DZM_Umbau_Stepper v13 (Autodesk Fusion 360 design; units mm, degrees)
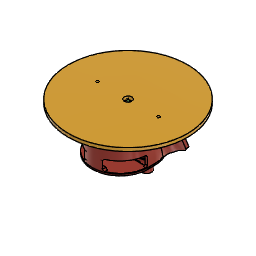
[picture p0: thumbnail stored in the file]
sketch "Skizze1" plane through (0, 0, 0) normal (0, 0, 1) x axis (1, 0, 0)
  line L1 (20.25, 0) -> (-20.25, 0)
  circle C1 centre (0, 0) radius 39.5
  circle C2 centre (0, 0) radius 2.5
  circle C3 centre (-20.25, 0) radius 0.925
  circle C4 centre (20.25, 0) radius 0.925
  point P1 (0, 0)
  point P2 (0, 0)
  point P3 (0, 0)
  point P4 (-20.25, 0)
  point P6 (-20.25, 0)
  point P5 (20.25, 0)
  point P7 (20.25, 0)
  point P8 (-20.25, 0)
  point P9 (20.25, 0)
  coincident P1 P2
  coincident P1 P3
  coincident P4 P6
  coincident P5 P7
  horizontal L1
  coincident P4 P8
  coincident P7 P9
  dimension "d1" diameter C1 = 79
  dimension "d2" diameter C2 = 5
  dimension "d3" distance P4 P5 = 40.5
  dimension "d4" distance P2 P4 = 20.25 (= "( 40.5 / 2 ) * 1 mm")
  dimension "d5" diameter C3 = 1.85
  dimension "d6" diameter C4 = 1.85
extrude "Extrusion1" new body sketch "Skizze1" profile of C1 C2 C3 C4 along normal blind 2.2 bodies "Tachoscheibe"
sketch "Skizze2" plane through (0, 0, 0) normal (0, 1, 0) x axis (1, 0, 0)
  circle C1 centre (-8.25, 8.8116) radius 1.3
  circle C2 centre (8.25, 8.8116) radius 1.3
  circle C3 centre (0, -10.5) radius 1.3
  circle C4 centre (0, 6.3) radius 0.95
  circle C5 centre (-13.5, 0) radius 1
  circle C6 centre (13.5, 0) radius 1
  circle C7 centre (0, 0) radius 16
  circle C8 centre (12, 3.9) radius 0.25
  circle C9 centre (12, -3.9) radius 0.25
  circle C10 centre (-12, 3.9) radius 0.25
  circle C11 centre (-12, -3.9) radius 0.25
  point P1 (0, 0)
  point P4 (0, -10.5)
  point P5 (0, 6.3)
  point P8 (0, 0)
  point P6 (-13.5, 0)
  point P7 (13.5, 0)
  point P2 (-8.25, 8.8116)
  point P3 (8.25, 8.8116)
  point P9 (12, 3.9)
  point P10 (12, -3.9)
  point P11 (-12, 3.9)
  point P12 (-12, -3.9)
  equal C1 C3
  equal C2 C3
  vertical P1 P4
  vertical P1 P5
  coincident P1 P8
  horizontal P6 P8
  horizontal P7 P8
  equal C8 C9
  equal C8 C10
  equal C8 C11
  dimension "d9" distance P2 P3 = 16.5
  dimension "d10" distance P1 P2 = 8.25 (= "( 16.5 / 2 ) * 1 mm")
  dimension "d11" distance P2 P4 = 21
  dimension "d12" distance P3 P4 = 21
  dimension "d13" diameter C3 = 2.6
  dimension "d18" diameter C4 = 1.9
  dimension "d19" distance P6 P7 = 27
  dimension "d20" distance P1 P6 = 13.5 (= "( 27 / 2 ) * 1 mm")
  dimension "d21" diameter C5 = 2
  dimension "d22" diameter C6 = 2
  dimension "d23" diameter C7 = 32
  dimension "d24" distance P1 P4 = 10.5
  dimension "d25" distance P9 P10 = 7.8
  dimension "d26" distance P1 P9 = 3.9 (= "( 7.8 / 2 ) * 1 mm")
  dimension "d27" distance P11 P12 = 7.8
  dimension "d28" distance P1 P11 = 3.9 (= "( 7.8 / 2 ) * 1 mm")
  dimension "d29" distance P1 P10 = 12
  dimension "d30" distance P8 P12 = 12
  dimension "d31" diameter C8 = 0.5
  dimension "d32" distance P8 P11 = 12
  dimension "d33" distance P8 P9 = 12
  dimension "d201" distance P1 P5 = 6.3
extrude "Extrusion2" new body sketch "Skizze2" along normal blind 9.5 bodies "Steppermotor"
extrude "Extrusion3" add sketch "Skizze2" profile of C1 C2 C3 along normal blind 13.3 (= "3.8 mm + 9.5 mm")
extrude "Extrusion4" add sketch "Skizze2" profile of C4 along normal blind 11.4 (= "9.5 mm + 1.9 mm")
sketch "Skizze3" plane through (0, 11.4, 0) normal (0, 1, 0) x axis (-1, 0, 0)
  circle C1 centre (0, -6.3) radius 0.95
  circle C2 centre (0, -6.3) radius 0.5
  concentric C1 C2
  dimension "d40" diameter C2 = 1
extrude "Extrusion5" add sketch "Skizze3" profile of C2 along normal blind 9
extrude "Extrusion6" add sketch "Skizze2" profile of C8 C9 C10 C11 along normal blind 12.5 (= "9.5 mm + 3 mm")
move "Verschieben1"
sketch "Skizze4" plane through (0, 0, -3.8628) normal (0, 0, 1) x axis (-1, 0, 0)
  circle C1 centre (0, 16.0521) radius 1.3
  circle C2 centre (-8.25, -3.2595) radius 1.3
  circle C3 centre (-12, 9.4521) radius 0.25
  circle C4 centre (0, -0.7479) radius 0.95
  circle C5 centre (13.5, 5.5521) radius 1
  circle C6 centre (-12, 1.6521) radius 0.25
  circle C7 centre (12, 9.4521) radius 0.25
  circle C8 centre (-13.5, 5.5521) radius 1
  circle C9 centre (12, 1.6521) radius 0.25
  circle C10 centre (8.25, -3.2595) radius 1.3
  circle C11 centre (0, 5.5521) radius 16
  circle C12 centre (13.5, 5.5521) radius 0.85
  circle C13 centre (-13.5, 5.5521) radius 0.85
  concentric C5 C12
  concentric C8 C13
  dimension "d47" diameter C12 = 1.7
  dimension "d48" diameter C13 = 1.7
extrude "Extrusion8" new body sketch "Skizze4" along normal blind 8.5
move "Verschieben3"
sketch "Skizze5" plane through (0, 0, 4.6372) normal (0, 0, -1) x axis (1, 0, 0)
  circle C1 centre (20.25, -0.7479) radius 0.925
  circle C2 centre (0, -0.7479) radius 2.5
  circle C3 centre (-20.25, -0.7479) radius 0.925
  circle C4 centre (0, -0.7479) radius 39.5
  circle C5 centre (20.25, -0.7479) radius 0.925
  circle C6 centre (-20.25, -0.7479) radius 0.925
  circle C7 centre (0, 5.5521) radius 16
  circle C8 centre (-20.25, -0.7479) radius 0.8
  circle C9 centre (20.25, -0.7479) radius 0.8
  circle C10 centre (-20.25, -0.7479) radius 3
  circle C11 centre (20.25, -0.7479) radius 3
  circle C12 centre (0, 4) radius 18.25
  arc A1 centre (-30.2824, 11.7161) radius 13 clockwise from (-17.6849, 8.5062) to (-22.1311, 1.5891)
  arc A2 centre (-21.8165, -13.1494) radius 9.5 clockwise from (-20.626, -3.7243) to (-14.3478, -7.2784)
  arc A3 centre (30.2824, 11.7161) radius 13 clockwise from (22.1311, 1.5891) to (17.6849, 8.5062)
  arc A4 centre (21.8165, -13.1494) radius 9.5 clockwise from (14.3478, -7.2784) to (20.626, -3.7243)
  point P1 (0, 0)
  point P12 (0, 4)
  point P14 (-22.1311, 1.5891)
  point P13 (-17.6849, 8.5062)
  point P17 (-14.3478, -7.2784)
  point P16 (-20.626, -3.7243)
  point P20 (22.1311, 1.5891)
  point P19 (17.6849, 8.5062)
  point P23 (20.626, -3.7243)
  point P22 (14.3478, -7.2784)
  concentric C6 C8
  concentric C5 C9
  concentric C6 C10
  concentric C9 C11
  vertical P1 P12
  tangent C12 A1
  coincident C10 P14
  coincident C12 P13
  tangent C12 A2
  coincident C12 P17
  coincident C10 P16
  tangent C12 A3
  coincident C11 P20
  coincident C12 P19
  tangent C12 A4
  coincident C11 P23
  coincident C12 P22
  tangent C10 A1
  tangent C10 A2
  tangent C11 A4
  tangent C11 A3
  dimension "d51" diameter C8 = 1.6
  dimension "d52" diameter C9 = 1.6
  dimension "d53" diameter C10 = 6
  dimension "d54" diameter C11 = 6
  dimension "d55" diameter C12 = 36.5
  dimension "d56" distance P1 P12 = 4
  dimension "d57" radius A4 = 9.5
  dimension "d58" radius A2 = 9.5
  dimension "d59" radius A3 = 13
  dimension "d60" radius A1 = 13
sketch "Skizze6" plane through (0, 0, 4.6372) normal (0, 0, 1) x axis (-1, 0, 0)
  circle C1 centre (8.25, -3.2595) radius 1.3
  circle C2 centre (0, -0.7479) radius 0.95
  circle C3 centre (-8.25, -3.2595) radius 1.3
  circle C4 centre (13.5, 5.5521) radius 0.85
  circle C5 centre (0, 16.0521) radius 1.3
  circle C6 centre (-13.5, 5.5521) radius 0.85
  circle C7 centre (0, 5.5521) radius 16
  arc A1 centre (21.8165, -13.1494) radius 9.5 clockwise from (14.3478, -7.2784) to (20.626, -3.7243)
  circle C8 centre (0, 4) radius 18.25
  circle C9 centre (20.25, -0.7479) radius 3
  arc A2 centre (30.2824, 11.7161) radius 13 clockwise from (22.1311, 1.5891) to (17.6849, 8.5062)
  arc A3 centre (-30.2824, 11.7161) radius 13 clockwise from (-17.6849, 8.5062) to (-22.1311, 1.5891)
  circle C10 centre (-20.25, -0.7479) radius 3
  arc A4 centre (-21.8165, -13.1494) radius 9.5 clockwise from (-20.626, -3.7243) to (-14.3478, -7.2784)
  circle C11 centre (-20.25, -0.7479) radius 0.8
  circle C12 centre (20.25, -0.7479) radius 0.8
extrude "Extrusion9" add sketch "Skizze6" profile of C7 A1 C8 C9 A2 A3 C10 A4 C11 C12 against normal blind 3
sketch "Skizze7" plane through (0, 0, -3.8628) normal (0, 0, 1) x axis (-1, 0, 0)
  line L1 (-1.5, 0.6521) -> (-13.5, 0.6521)
  line L2 (-1.5, 10.4521) -> (-1.5, 0.6521)
  line L3 (-13.5, 10.4521) -> (-1.5, 10.4521)
  line L4 (-13.5, 0.6521) -> (-13.5, 10.4521)
  line L5 (13.5, 0.6521) -> (1.5, 0.6521)
  line L6 (13.5, 10.4521) -> (13.5, 0.6521)
  line L7 (1.5, 10.4521) -> (13.5, 10.4521)
  line L8 (1.5, 0.6521) -> (1.5, 10.4521)
  line L9 (-5.5, 0.6521) -> (-1.5, 0.6521)
  line L10 (-5.5, -10.8203) -> (-5.5, 0.6521)
  line L11 (-1.5, -10.8203) -> (-5.5, -10.8203)
  line L12 (-1.5, 0.6521) -> (-1.5, -10.8203)
  line L13 (5.5, 0.6521) -> (1.5, 0.6521)
  line L14 (5.5, -11.2243) -> (5.5, 0.6521)
  line L15 (1.5, -11.2243) -> (5.5, -11.2243)
  line L16 (1.5, 0.6521) -> (1.5, -11.2243)
  circle C1 centre (-13.5, 5.5521) radius 2
  circle C2 centre (13.5, 5.5521) radius 2
  circle C3 centre (0, 0) radius 1.3
  point P2 (-13.5, 5.5521)
  point P8 (-13.5, 5.5521)
  point P3 (13.5, 5.5521)
  point P9 (13.5, 5.5521)
  point P1 (0, 0)
  point P24 (0, 0)
  point P5 (-12, 1.6521)
  point P4 (-12, 9.4521)
  point P7 (12, 9.4521)
  point P6 (12, 1.6521)
  point P14 (1.5, 0.6521)
  point P15 (13.5, 0.6521)
  point P12 (-1.5, 10.4521)
  point P13 (-13.5, 10.4521)
  point P11 (-1.5, 0.6521)
  point P18 (-5.5, 0.6521)
  point P21 (5.5, 0.6521)
  coincident P2 P8
  coincident P3 P9
  horizontal L1
  vertical L2
  horizontal L3
  vertical L4
  horizontal L5
  vertical L6
  horizontal L7
  vertical L8
  coincident P2 L4
  coincident P3 L6
  horizontal L9
  vertical L10
  horizontal L11
  vertical L12
  horizontal L13
  vertical L14
  horizontal L15
  vertical L16
  coincident P1 P24
  dimension "d63" diameter C1 = 4
  dimension "d64" diameter C2 = 4
  dimension "d65" distance P5 L1 = 1
  dimension "d66" distance P4 L3 = 1
  dimension "d67" distance P7 L7 = 1
  dimension "d68" distance P6 L5 = 1
  dimension "d69" distance P14 P15 = 12
  dimension "d70" distance P12 P13 = 12
  dimension "d73" distance P11 P18 = 4
  dimension "d74" distance P14 P21 = 4
  dimension "d79" diameter C3 = 2.6
extrude "Extrusion10" cut sketch "Skizze7" profile of C1 C2 L1 L2 L3 L4 L5 L6 L7 L8 L9 L10 L11 L12 L13 L14 L15 L16 along normal blind 2
fillet "Abrundung1" radius 2.5
fillet "Abrundung2" radius 1
extrude "Extrusion11" cut sketch "Skizze7" profile of C3 along normal blind 9
work_plane "Arbeitsebene1" AlongDistance 26.2
sketch "Skizze8" plane through (0, 0, -21.5628) normal (0, 0, -1) x axis (-1, 0, 0)
  line L1 (2.0207, 16.0535) -> (4.0415, 12.5535)
  line L2 (-2.0207, 16.0535) -> (2.0207, 16.0535)
  line L3 (-4.0415, 12.5535) -> (-2.0207, 16.0535)
  line L4 (-2.0207, 9.0535) -> (-4.0415, 12.5535)
  line L5 (2.0207, 9.0535) -> (-2.0207, 9.0535)
  line L6 (4.0415, 12.5535) -> (2.0207, 9.0535)
  line L7 (-9.4, 2.0207) -> (-9.4, -2.0207)
  line L8 (-12.9, 4.0415) -> (-9.4, 2.0207)
  line L9 (-16.4, 2.0207) -> (-12.9, 4.0415)
  line L10 (-16.4, -2.0207) -> (-16.4, 2.0207)
  line L11 (-12.9, -4.0415) -> (-16.4, -2.0207)
  line L12 (-9.4, -2.0207) -> (-12.9, -4.0415)
  line L13 (12.9, -4.0415) -> (9.4, -2.0207)
  line L14 (16.4, -2.0207) -> (12.9, -4.0415)
  line L15 (16.4, 2.0207) -> (16.4, -2.0207)
  line L16 (12.9, 4.0415) -> (16.4, 2.0207)
  line L17 (9.4, 2.0207) -> (12.9, 4.0415)
  line L18 (9.4, -2.0207) -> (9.4, 2.0207)
  line L19 (0, 4) -> (0, -5)
  line L20 (8, 0) -> (-6, 0)
  line L21 (18.5, 0) -> (18.5, -4.5)
  line L22 (-18.5, 0) -> (-18.5, -4.5)
  circle C1 centre (0, 0) radius 18.5
  circle C2 centre (12.9, 0) radius 3.5
  circle C3 centre (-12.9, 0) radius 3.5
  circle C4 centre (0, 12.5535) radius 3.5
  circle C5 centre (0, -4.5) radius 18.5
  point P1 (0, 0)
  point P2 (0, 0)
  point P5 (0, 12.5535)
  point P4 (-12.9, 0)
  point P12 (0, 12.5535)
  point P19 (-12.9, 0)
  point P3 (12.9, 0)
  point P26 (12.9, 0)
  point P31 (0, -4.5)
  point P32 (18.5, -4.5)
  point P33 (18.5, 0)
  point P34 (-18.5, -4.5)
  point P35 (-18.5, 0)
  point P16 (-16.4, 2.0207)
  coincident P1 P2
  vertical P1 P5
  horizontal P1 P4
  coincident P5 P12
  coincident P4 P19
  coincident P3 P26
  vertical L19
  parallel L18 L19
  parallel L7 L19
  perpendicular L19 L20
  parallel L5 L20
  vertical P2 P31
  coincident L19 P31
  coincident C5 P32
  coincident C1 P33
  tangent C5 L21
  tangent C1 L21
  coincident C5 P34
  coincident C1 P35
  vertical L22
  tangent C1 L22
  dimension "d83" diameter C1 = 37
  dimension "d84" distance P2 P3 = 12.9 (= "( 25.8 / 2 ) * 1 mm")
  dimension "d85" distance P3 P4 = 25.8
  dimension "d86" distance P3 P5 = 18
  dimension "d87" distance P4 P5 = 18
  dimension "d88" diameter C2 = 7
  dimension "d89" diameter C3 = 7
  dimension "d90" diameter C4 = 7
  dimension "d103" distance P12 L6 = 3.5 (= "( 7 / 2 ) * 1 mm")
  dimension "d104" distance P19 L12 = 3.5
  dimension "d105" distance P26 L18 = 3.5
  dimension "d109" diameter C5 = 37
  dimension "d110" distance P2 P31 = 4.5
  dimension "d171" diameter P16 = 1.3
extrude "Extrusion12" new body sketch "Skizze8" profile of C2 C3 C4 along normal blind 5
extrude "Extrusion13" add sketch "Skizze8" profile of C1 C2 C3 C4 L1 L2 L3 L4 L5 L6 L7 L8 L9 L10 L11 L12 L13 L14 L15 L16 L17 L18 C5 L21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 against normal blind 1
sketch "Skizze9" plane through (0, 0, 1.6372) normal (0, 0, -1) x axis (1, 0, 0)
  circle C1 centre (0, 5.5521) radius 16
  circle C2 centre (-20.25, -0.7479) radius 0.8
  circle C3 centre (20.25, -0.7479) radius 0.8
  arc A1 centre (-20.25, -0.7479) radius 3 clockwise from (-20.626, -3.7243) to (-22.1311, 1.5891)
  arc A2 centre (-21.8165, -13.1494) radius 9.5 clockwise from (-20.626, -3.7243) to (-14.3478, -7.2784)
  arc A3 centre (0, 4) radius 18.25 clockwise from (14.3478, -7.2784) to (-14.3478, -7.2784)
  arc A4 centre (21.8165, -13.1494) radius 9.5 clockwise from (14.3478, -7.2784) to (20.626, -3.7243)
  arc A5 centre (20.25, -0.7479) radius 3 clockwise from (22.1311, 1.5891) to (20.626, -3.7243)
  arc A6 centre (30.2824, 11.7161) radius 13 clockwise from (22.1311, 1.5891) to (17.6849, 8.5062)
  arc A7 centre (0, 4) radius 18.25 clockwise from (-17.6849, 8.5062) to (17.6849, 8.5062)
  arc A8 centre (-30.2824, 11.7161) radius 13 clockwise from (-17.6849, 8.5062) to (-22.1311, 1.5891)
  arc A9 centre (0, 5.5521) radius 16 clockwise from (-5.5, -9.4729) to (5.5, -9.4729)
  circle C4 centre (0, 5.5521) radius 16
  circle C5 centre (0, 5.5521) radius 17.5
  concentric A9 C4
  dimension "d95" = 1.5
work_plane "Arbeitsebene2" AlongDistance -7
sketch "Skizze10" plane through (0, 0, -14.5628) normal (0, 0, -1) x axis (-1, 0, 0)
  line L1 (18.5, 0) -> (18.5, -4.5)
  line L2 (-18.5, -4.5) -> (-18.5, 0)
  line L3 (-17, -4.5) -> (-17, 0)
  line L4 (17, 0) -> (17, -4.5)
  arc A1 centre (0, 0) radius 18.5 clockwise from (-18.5, 0) to (18.5, 0)
  arc A2 centre (0, -4.5) radius 18.5 clockwise from (18.5, -4.5) to (-18.5, -4.5)
  circle C1 centre (-12.9, 0) radius 3.5
  circle C2 centre (12.9, 0) radius 3.5
  circle C3 centre (0, 12.5535) radius 3.5
  arc A3 centre (0, 0) radius 17 clockwise from (-17, 0) to (17, 0)
  arc A4 centre (0, -4.5) radius 17 clockwise from (17, -4.5) to (-17, -4.5)
  dimension "d119" = -1.5
work_plane "Arbeitsebene3" AlongDistance 0
sketch "Skizze15" plane through (0, 0, -3.8628) normal (0, 0, -1) x axis (-1, 0, 0)
  arc A1 centre (0, -5.5521) radius 16 clockwise from (5.5, 9.4729) to (-5.5, 9.4729)
  circle C1 centre (0, -5.5521) radius 16
  circle C2 centre (0, -5.5521) radius 17.5
  point P2 (-5.5, 9.4729)
  concentric A1 C1
  coincident P2 C1
sketch "Skizze16" plane through (0, 0, -20.5628) normal (0, 0, 1) x axis (-1, 0, 0)
  line L1 (18.5, 4.5) -> (18.5, 0)
  line L2 (-18.5, 0) -> (-18.5, 4.5)
  line L3 (-18.5, 4.5) -> (-18.5, 0)
  line L4 (18.5, 0) -> (18.5, 4.5)
  line L5 (17, 0) -> (17, 4.5)
  line L6 (-17, 4.5) -> (-17, 0)
  arc A1 centre (0, 4.5) radius 18.5 clockwise from (-18.5, 4.5) to (18.5, 4.5)
  arc A2 centre (0, 0) radius 18.5 clockwise from (18.5, 0) to (-18.5, 0)
  arc A3 centre (0, 4.5) radius 18.5 clockwise from (-18.5, 4.5) to (18.5, 4.5)
  arc A4 centre (0, 0) radius 18.5 clockwise from (18.5, 0) to (-18.5, 0)
  arc A5 centre (0, 4.5) radius 17 clockwise from (-17, 4.5) to (17, 4.5)
  arc A6 centre (0, 0) radius 17 clockwise from (17, 0) to (-17, 0)
loft "Erhebung4" sketch "Skizze15" + "Skizze9"
loft "Erhebung5" sketch "Skizze10"
shell "Schale" innerThickness 1.5
sketch "Skizze17" plane through (0, 0, -20.0628) normal (0, 0, 1) x axis (-1, 0, 0)
  line L1 (12.9, -4.0415) -> (9.4, -2.0207)
  line L2 (16.4, -2.0207) -> (12.9, -4.0415)
  line L3 (16.4, 2.0207) -> (16.4, -2.0207)
  line L4 (12.9, 4.0415) -> (16.4, 2.0207)
  line L5 (9.4, 2.0207) -> (12.9, 4.0415)
  line L6 (9.4, -2.0207) -> (9.4, 2.0207)
  line L7 (-2.0207, -16.0535) -> (-4.0415, -12.5535)
  line L8 (2.0207, -16.0535) -> (-2.0207, -16.0535)
  line L9 (4.0415, -12.5535) -> (2.0207, -16.0535)
  line L10 (2.0207, -9.0535) -> (4.0415, -12.5535)
  line L11 (-2.0207, -9.0535) -> (2.0207, -9.0535)
  line L12 (-4.0415, -12.5535) -> (-2.0207, -9.0535)
  line L13 (-9.4, 2.0207) -> (-9.4, -2.0207)
  line L14 (-12.9, 4.0415) -> (-9.4, 2.0207)
  line L15 (-16.4, 2.0207) -> (-12.9, 4.0415)
  line L16 (-16.4, -2.0207) -> (-16.4, 2.0207)
  line L17 (-12.9, -4.0415) -> (-16.4, -2.0207)
  line L18 (-9.4, -2.0207) -> (-12.9, -4.0415)
  line L19 (0, 6) -> (0, -5)
  line L20 (-4, 0) -> (5, 0)
  curve K1 (17.0128, 1.4501) -> (17.0128, 1.4501)
  circle C1 centre (0, -12.5535) radius 2
  circle C2 centre (12.9, 0) radius 2
  circle C3 centre (-12.9, 0) radius 2
  circle C4 centre (0, -12.5535) radius 4.5
  circle C5 centre (12.9, 0) radius 4.5
  circle C6 centre (-12.9, 0) radius 4.5
  circle C7 centre (12.9, 0) radius 3.5
  circle C8 centre (-12.9, 0) radius 3.5
  circle C9 centre (0, -12.5535) radius 3.5
  point P3 (12.9, 0)
  point P11 (12.9, 0)
  point P4 (-12.9, 0)
  point P25 (-12.9, 0)
  point P18 (0, -12.5535)
  coincident P3 P11
  coincident P4 P25
  vertical L19
  horizontal L20
  parallel L11 L20
  parallel L6 L19
  parallel L13 L19
  concentric C1 C4
  concentric C2 C5
  concentric C3 C6
  dimension "d121" distance P11 L6 = 3.5
  dimension "d122" distance P18 L12 = 3.5
  dimension "d123" distance P25 L18 = 3.5
  dimension "d124" diameter C4 = 9
  dimension "d125" diameter C5 = 9
  dimension "d126" diameter C6 = 9
extrude "Extrusion17" add sketch "Skizze17" profile of L1 L2 L3 L4 L5 L6 L7 L8 L9 L10 L11 L12 L13 L14 L15 L16 L17 L18 C4 C5 C6 along normal blind 3
sketch "Skizze18" plane through (0, 0, -26.5628) normal (0, 0, -1) x axis (1, 0, 0)
  circle C1 centre (0, -12.5535) radius 3.5
  circle C2 centre (12.9, 0) radius 3.5
  circle C3 centre (-12.9, 0) radius 3.5
  circle C4 centre (12.9, 0) radius 2.1
  circle C5 centre (0, -12.5535) radius 2.1
  circle C6 centre (-12.9, 0) radius 2.1
  concentric C2 C4
  concentric C1 C5
  concentric C3 C6
  equal C4 C5
  equal C4 C6
  dimension "d134" diameter C4 = 4.2
extrude "Extrusion18" cut sketch "Skizze18" profile of C4 C5 C6 against normal blind 6
fillet "Abrundung5" radius 2
sketch "Skizze20" plane through (0, 0, 0) normal (1, 0, 0) x axis (0, 1, 0)
  line L1 (18.5, -20.5628) -> (11.9479, -3.8628)
  line L2 (0, -20.5628) -> (18.5, -20.5628)
  line L3 (-21.9872, -3.8628) -> (11.9479, -3.8628)
  point P3 (18.5, -20.5628)
  point P2 (11.9479, -3.8628)
  point P4 (18.5, -20.5628)
  point P6 (11.9479, -3.8628)
  coincident P3 L2
  coincident P2 L3
  coincident P3 P4
  coincident P2 P6
work_plane "Arbeitsebene5" RotateAngle 90
sketch "Skizze21" plane through (0, 9.0407, 3.547) normal (0, -0.9309, -0.3652) x axis (0, 0.3652, -0.9309)
  line L1 (5, 22.5) -> (25, 22.5)
  line L2 (5, -22.5) -> (5, 22.5)
  line L3 (25, -22.5) -> (5, -22.5)
  line L4 (25, 22.5) -> (25, -22.5)
  line L5 (5, -22.5) -> (25, 22.5)
  line L6 (25, -22.5) -> (5, 22.5)
  point P6 (15, 0)
  point P1 (0, 0)
  point P4 (5, -22.5)
  point P5 (25, -22.5)
  point P3 (5, 22.5)
  horizontal L1
  perpendicular L1 L2
  parallel L1 L3
  parallel L2 L4
  coincident L5 P6
  coincident L6 P6
  horizontal P1 P6
  dimension "d141" distance P4 P5 = 20
  dimension "d142" distance P3 P4 = 45
extrude "Extrusion19" add sketch "Skizze21" profile of L1 L2 L3 L4 along normal blind 1 and against normal blind 1
delete_face "Fläche löschen9"
fillet "Abrundung6" radius 8
work_plane "Arbeitsebene6" AlongDistance 9.508
sketch "Skizze22" plane through (0, 9.508, 0) normal (0, 1, 0) x axis (1, 0, 0)
  line L1 (5.5, 1.8628) -> (1.5, 1.8628)
  line L2 (5.5, 1.8628) -> (5.5, 3.8628)
  line L3 (1.5, 3.8628) -> (1.5, 1.8628)
  line L4 (-1.5, 1.8628) -> (-1.5, 3.8628)
  line L5 (-1.5, 1.8628) -> (-5.5, 1.8628)
  line L6 (-5.5, 3.8628) -> (-5.5, 1.8628)
  line L7 (1.5, 3.8628) -> (5.5, 3.8628)
  line L8 (-5.5, 3.8628) -> (-1.5, 3.8628)
  point P4 (5.5, 3.8628)
  point P10 (5.5, 3.8628)
  point P5 (1.5, 3.8628)
  point P11 (1.5, 3.8628)
  point P6 (-1.5, 3.8628)
  point P12 (-1.5, 3.8628)
  point P9 (-5.5, 3.8628)
  point P13 (-5.5, 3.8628)
  coincident P4 P10
  coincident P5 P11
  coincident P6 P12
  coincident P9 P13
extrude "Extrusion20" cut sketch "Skizze22" along normal blind 5
fillet "Abrundung7" radius 2
delete_face "Fläche löschen11"
delete_face "Fläche löschen12"
sketch "Skizze23" plane through (0, 9.9717, 3.9123) normal (0, 0.9309, 0.3652) x axis (-1, 0, 0)
  line L1 (-1.5, -8.3521) -> (-1.5, -6.2036)
  line L2 (-5.5, -8.3521) -> (-1.5, -8.3521)
  line L3 (-5.5, -6.2036) -> (-5.5, -8.3521)
  line L4 (-1.5, -6.2036) -> (-5.5, -6.2036)
  line L5 (5.5, -8.3521) -> (5.5, -6.2036)
  line L6 (1.5, -8.3521) -> (5.5, -8.3521)
  line L7 (1.5, -6.2036) -> (1.5, -8.3521)
  line L8 (5.5, -6.2036) -> (1.5, -6.2036)
  line L9 (-6.0757, -2.4439) -> (-6.0625, -2.4439)
  curve K1 (-6.0757, -2.4439) -> (-10.2002, -5)
  line L10 (-22.5, -5) -> (-10.2002, -5)
  line L11 (-22.5, -25) -> (-22.5, -5)
  line L12 (22.5, -25) -> (-22.5, -25)
  line L13 (22.5, -5) -> (22.5, -25)
  line L14 (10.2002, -5) -> (22.5, -5)
  curve K2 (10.2002, -5) -> (6.0757, -2.4439)
  line L15 (6.0625, -2.4439) -> (6.0757, -2.4439)
  line L16 (-1.5, -6.2036) -> (-5.5, -6.2036)
  line L17 (-5.5, -6.2036) -> (-5.5, -8.3521)
  line L18 (-5.5, -8.3521) -> (-1.5, -8.3521)
  line L19 (-1.5, -8.3521) -> (-1.5, -6.2036)
  line L20 (1.5, -6.2036) -> (1.5, -8.3521)
  line L21 (5.5, -6.2036) -> (1.5, -6.2036)
  line L22 (5.5, -8.3521) -> (5.5, -6.2036)
  line L23 (1.5, -8.3521) -> (5.5, -8.3521)
  line L24 (-5.5, -6.2036) -> (-1.5, -6.2036)
  line L25 (-5.5, -2.983) -> (-5.5, -6.2036)
  line L26 (-1.5, -2.983) -> (-5.5, -2.983)
  line L27 (-1.5, -6.2036) -> (-1.5, -2.983)
  line L28 (5.5, -6.2036) -> (1.5, -6.2036)
  line L29 (5.5, -2.983) -> (5.5, -6.2036)
  line L30 (1.5, -2.983) -> (5.5, -2.983)
  line L31 (1.5, -6.2036) -> (1.5, -2.983)
  closed curve K3 centre (0, 42.5034)
  point P31 (-5.5, -2.983)
  point P22 (-1.5, -6.2036)
  point P29 (-1.5, -6.2036)
  point P35 (5.5, -2.983)
  point P9 (1.5, -6.2036)
  point P33 (1.5, -6.2036)
  point P21 (-5.5, -6.2036)
  point P30 (-5.5, -6.2036)
  point P27 (5.5, -6.2036)
  point P34 (5.5, -6.2036)
  horizontal L24
  vertical L25
  horizontal L26
  vertical L27
  coincident K3 P31
  coincident P22 P29
  horizontal L28
  vertical L29
  horizontal L30
  vertical L31
  coincident K3 P35
  coincident P9 P33
  coincident P21 P30
  coincident P27 P34
extrude "Extrusion21" cut sketch "Skizze23" profile of L4 L8 K3 L16 L21 L24 L25 L26 L27 L28 L29 L30 L31 against normal blind 3
sketch "Skizze24" plane through (0, 9.9717, 3.9123) normal (0, 0.9309, 0.3652) x axis (-1, 0, 0)
  line L1 (-5.5, -2.983) -> (-5.5, -8.3521)
  line L2 (-6.0757, -2.4439) -> (-6.0625, -2.4439)
  curve K1 (-6.0757, -2.4439) -> (-10.2002, -5)
  line L3 (-22.5, -5) -> (-10.2002, -5)
  line L4 (-22.5, -25) -> (-22.5, -5)
  line L5 (22.5, -25) -> (-22.5, -25)
  line L6 (22.5, -5) -> (22.5, -25)
  line L7 (10.2002, -5) -> (22.5, -5)
  curve K2 (10.2002, -5) -> (6.0757, -2.4439)
  line L8 (6.0625, -2.4439) -> (6.0757, -2.4439)
  line L9 (5.5, -8.3521) -> (5.5, -2.983)
  line L10 (1.5, -8.3521) -> (5.5, -8.3521)
  line L11 (1.5, -5.2346) -> (1.5, -8.3521)
  line L12 (-1.5, -8.3521) -> (-1.5, -5.2346)
  line L13 (-5.5, -8.3521) -> (-1.5, -8.3521)
  line L14 (22.5, -5) -> (-22.5, -25)
  line L15 (-22.5, -5) -> (22.5, -25)
  line L16 (-20.25, -7.5) -> (20.25, -7.5)
  line L17 (-20.25, -22.5) -> (-20.25, -7.5)
  line L18 (20.25, -22.5) -> (-20.25, -22.5)
  line L19 (20.25, -7.5) -> (20.25, -22.5)
  line L20 (-20.25, -22.5) -> (20.25, -7.5)
  line L21 (20.25, -22.5) -> (-20.25, -7.5)
  closed curve K3 centre (0, 42.5034)
  circle C1 centre (20.25, -7.5) radius 0.5
  circle C2 centre (20.25, -22.5) radius 0.5
  circle C3 centre (-20.25, -7.5) radius 0.5
  circle C4 centre (-20.25, -22.5) radius 0.5
  closed curve K4 centre (0, 42.5034)
  closed curve K5 centre (0, 42.5034)
  point P9 (-22.5, -25)
  point P23 (-22.5, -25)
  point P11 (22.5, -5)
  point P24 (22.5, -5)
  point P10 (22.5, -25)
  point P25 (22.5, -25)
  point P8 (-22.5, -5)
  point P26 (-22.5, -5)
  point P27 (0, -15)
  point P32 (0, -15)
  point P28 (20.25, -7.5)
  point P33 (20.25, -7.5)
  point P31 (20.25, -22.5)
  point P34 (20.25, -22.5)
  point P29 (-20.25, -7.5)
  point P35 (-20.25, -7.5)
  point P30 (-20.25, -22.5)
  point P36 (-20.25, -22.5)
  coincident P9 P23
  coincident P11 P24
  coincident P10 P25
  coincident P8 P26
  midpoint L15 P27
  horizontal L16
  perpendicular L16 L17
  parallel L16 L18
  parallel L17 L19
  coincident L20 P32
  coincident L21 P32
  coincident P27 P32
  coincident P28 P33
  coincident P31 P34
  coincident P29 P35
  coincident P30 P36
  dimension "d160" distance P30 P31 = 40.5
  dimension "d161" distance P29 P30 = 15
  dimension "d162" diameter C1 = 1
  dimension "d163" diameter C2 = 1
  dimension "d164" diameter C3 = 1
  dimension "d165" diameter C4 = 1
extrude "Extrusion22" cut sketch "Skizze24" profile of C1 C2 C3 C4 against normal blind 2
sketch "Skizze25" plane through (0, 0, 4.6372) normal (0, 0, 1) x axis (-1, 0, 0)
  arc A1 centre (20.25, -0.7479) radius 3 clockwise from (22.1311, 1.5891) to (20.626, -3.7243)
  arc A2 centre (30.2824, 11.7161) radius 13 clockwise from (22.1311, 1.5891) to (17.6849, 8.5062)
  arc A3 centre (0, 4) radius 18.25 clockwise from (-17.6849, 8.5062) to (17.6849, 8.5062)
  arc A4 centre (-30.2824, 11.7161) radius 13 clockwise from (-17.6849, 8.5062) to (-22.1311, 1.5891)
  arc A5 centre (-20.25, -0.7479) radius 3 clockwise from (-20.626, -3.7243) to (-22.1311, 1.5891)
  arc A6 centre (-21.8165, -13.1494) radius 9.5 clockwise from (-20.626, -3.7243) to (-14.3478, -7.2784)
  arc A7 centre (0, 4) radius 18.25 clockwise from (14.3478, -7.2784) to (-14.3478, -7.2784)
  arc A8 centre (21.8165, -13.1494) radius 9.5 clockwise from (14.3478, -7.2784) to (20.626, -3.7243)
  circle C1 centre (-20.25, -0.7479) radius 0.8
  circle C2 centre (20.25, -0.7479) radius 0.8
  circle C3 centre (-8.25, -3.2595) radius 1.3
  circle C4 centre (-13.5, 5.5521) radius 0.85
  circle C5 centre (13.5, 5.5521) radius 0.85
  circle C6 centre (8.25, -3.2595) radius 1.3
  circle C7 centre (0, 16.0521) radius 1.3
  arc A9 centre (0, 5.5521) radius 17.5 clockwise from (-6.8609, -10.5469) to (6.8609, -10.5469)
  arc A10 centre (0, 4) radius 18.25 clockwise from (-17.6849, 8.5062) to (17.6849, 8.5062)
  arc A11 centre (0, 0) radius 1.3 clockwise from (-0.9377, -0.9004) to (0.9377, -0.9004)
  arc A12 centre (0, -0.7479) radius 0.95 clockwise from (0.9377, -0.9004) to (-0.9377, -0.9004)
extrude "Extrusion23" add sketch "Skizze25" profile of A3 A9 A10 against normal blind 3
work_plane "Arbeitsebene7" AlongDistance 17.517
sketch "Skizze26" plane through (17.517, 0, 0) normal (1, 0, 0) x axis (0, 1, 0)
  circle C1 centre (-8, -1) radius 0.65
  point P1 (0, 0)
  point P2 (-8, -1)
  dimension "d171" diameter C1 = 1.3
  dimension "d172" distance P1 P2 = 8
  dimension "d173" distance P1 P2 = 1
extrude "Extrusion24" cut sketch "Skizze26" against normal blind 4
work_plane "Arbeitsebene8" AlongDistance -17.517
sketch "Skizze27" plane through (-17.517, 0, 0) normal (1, 0, 0) x axis (0, 1, 0)
  circle C1 centre (-8, -1) radius 0.6
  point P1 (0, 0)
  point P2 (-8, -1)
  dimension "d177" diameter C1 = 1.2
  dimension "d178" distance P1 P2 = 8
  dimension "d179" distance P1 P2 = 1
extrude "Extrusion25" cut sketch "Skizze27" along normal blind 4
fillet "Abrundung11" radius 1.5
sketch "Skizze28" plane through (0, 0, -21.5628) normal (0, 0, -1) x axis (1, 0, 0)
  line L1 (-12.6602, -13.4896) -> (-16.99, -13.4896)
  curve K1 (16.9925, -13.4896) -> (16.6838, -7.9939)
  line L2 (18.5, 4.5) -> (18.5, 0)
  line L3 (-18.5, 0) -> (-18.5, 4.5)
  curve K2 (-16.681, -7.9997) -> (-16.99, -13.4896)
  line L4 (16.9925, -13.4896) -> (12.6602, -13.4896)
  arc A1 centre (0, 0) radius 18.5 clockwise from (12.6602, -13.4896) to (-12.6602, -13.4896)
  arc A2 centre (0, 4.5) radius 18.5 clockwise from (-18.5, 4.5) to (18.5, 4.5)
  arc A3 centre (0, 0) radius 18.5 clockwise from (-16.681, -7.9997) to (-18.5, 0)
  circle C1 centre (0, 0) radius 3.5
  arc A4 centre (0, 0) radius 18.5 clockwise from (18.5, 0) to (16.6838, -7.9939)
  circle C2 centre (12.9, 0) radius 3.5
  circle C3 centre (-12.9, 0) radius 3.5
  circle C4 centre (0, -12.5535) radius 3.5
  concentric A1 C1
  dimension "d194" diameter C1 = 7
extrude "Extrusion26" cut sketch "Skizze28" profile of C1 against normal blind 2
fillet "Abrundung18" radius 2
work_plane "Arbeitsebene9" AlongDistance 0
split "Teilen" bodies "Fuss (3)", "Fuss (2)", "Fuss (1)"
delete_face "Fläche löschen13"
delete_face "Fläche löschen14"
delete_face "Fläche löschen15"
extrude "Extrusion27" cut of existing geometry blind -1
sketch "Skizze30" plane through (0, 0, -3.8628) normal (0, 0, -1) x axis (1, 0, 0)
  line L1 (-12.5, 0.6521) -> (-8, 0.6521)
  line L2 (-13.5, 3.5521) -> (-13.5, 1.6521)
  line L3 (-13.5, 9.4521) -> (-13.5, 7.5521)
  line L4 (-2.5, 10.4521) -> (-12.5, 10.4521)
  line L5 (-1.5, -10.3774) -> (-1.5, 9.4521)
  line L6 (1.5, 9.4521) -> (1.5, -10.3774)
  line L7 (12.5, 10.4521) -> (2.5, 10.4521)
  line L8 (13.5, 7.5521) -> (13.5, 9.4521)
  line L9 (13.5, 1.6521) -> (13.5, 3.5521)
  line L10 (8, 0.6521) -> (12.5, 0.6521)
  line L11 (5.5, -9.4729) -> (5.5, -1.8479)
  line L12 (-5.5, -1.8479) -> (-5.5, -9.4729)
  line L13 (-1.5, 9.4521) -> (-1.5, -10.3774)
  line L14 (-12.5, 10.4521) -> (-2.5, 10.4521)
  line L15 (-13.5, 7.5521) -> (-13.5, 9.4521)
  line L16 (-13.5, 1.6521) -> (-13.5, 3.5521)
  line L17 (-8, 0.6521) -> (-12.5, 0.6521)
  line L18 (-5.5, -9.4729) -> (-5.5, -1.8479)
  line L19 (5.5, -1.8479) -> (5.5, -9.4729)
  line L20 (12.5, 0.6521) -> (8, 0.6521)
  line L21 (13.5, 3.5521) -> (13.5, 1.6521)
  line L22 (13.5, 9.4521) -> (13.5, 7.5521)
  line L23 (2.5, 10.4521) -> (12.5, 10.4521)
  line L24 (1.5, -10.3774) -> (1.5, 9.4521)
  arc A1 centre (-8, -1.8479) radius 2.5 clockwise from (-8, 0.6521) to (-5.5, -1.8479)
  arc A2 centre (-12.5, 1.6521) radius 1 clockwise from (-12.5, 0.6521) to (-13.5, 1.6521)
  arc A3 centre (-13.5, 5.5521) radius 2 clockwise from (-13.5, 7.5521) to (-13.5, 3.5521)
  arc A4 centre (-12.5, 9.4521) radius 1 clockwise from (-13.5, 9.4521) to (-12.5, 10.4521)
  arc A5 centre (-2.5, 9.4521) radius 1 clockwise from (-2.5, 10.4521) to (-1.5, 9.4521)
  arc A6 centre (0, 5.5521) radius 16 clockwise from (1.5, -10.3774) to (-1.5, -10.3774)
  arc A7 centre (2.5, 9.4521) radius 1 clockwise from (1.5, 9.4521) to (2.5, 10.4521)
  arc A8 centre (12.5, 9.4521) radius 1 clockwise from (12.5, 10.4521) to (13.5, 9.4521)
  arc A9 centre (13.5, 5.5521) radius 2 clockwise from (13.5, 3.5521) to (13.5, 7.5521)
  arc A10 centre (12.5, 1.6521) radius 1 clockwise from (13.5, 1.6521) to (12.5, 0.6521)
  arc A11 centre (8, -1.8479) radius 2.5 clockwise from (5.5, -1.8479) to (8, 0.6521)
  arc A12 centre (0, 5.5521) radius 16 clockwise from (-5.5, -9.4729) to (5.5, -9.4729)
  circle C1 centre (0, 16.0521) radius 1.3
  circle C2 centre (-8.25, -3.2595) radius 1.3
  circle C3 centre (-13.5, 5.5521) radius 0.85
  circle C4 centre (13.5, 5.5521) radius 0.85
  circle C5 centre (8.25, -3.2595) radius 1.3
  circle C6 centre (8.25, -3.2595) radius 1.3
  circle C7 centre (-8.25, -3.2595) radius 1.3
  circle C8 centre (0, 16.0521) radius 1.3
  arc A13 centre (-2.5, 9.4521) radius 1 clockwise from (-2.5, 10.4521) to (-1.5, 9.4521)
  arc A14 centre (-12.5, 9.4521) radius 1 clockwise from (-13.5, 9.4521) to (-12.5, 10.4521)
  arc A15 centre (-13.5, 5.5521) radius 2 clockwise from (-13.5, 7.5521) to (-13.5, 3.5521)
  arc A16 centre (-12.5, 1.6521) radius 1 clockwise from (-12.5, 0.6521) to (-13.5, 1.6521)
  arc A17 centre (-8, -1.8479) radius 2.5 clockwise from (-8, 0.6521) to (-5.5, -1.8479)
  arc A18 centre (8, -1.8479) radius 2.5 clockwise from (5.5, -1.8479) to (8, 0.6521)
  arc A19 centre (12.5, 1.6521) radius 1 clockwise from (13.5, 1.6521) to (12.5, 0.6521)
  arc A20 centre (13.5, 5.5521) radius 2 clockwise from (13.5, 3.5521) to (13.5, 7.5521)
  arc A21 centre (12.5, 9.4521) radius 1 clockwise from (12.5, 10.4521) to (13.5, 9.4521)
  arc A22 centre (2.5, 9.4521) radius 1 clockwise from (1.5, 9.4521) to (2.5, 10.4521)
  circle C9 centre (8.25, -3.2595) radius 1.6
  circle C10 centre (-8.25, -3.2595) radius 1.6
  circle C11 centre (0, 16.0521) radius 1.6
  arc A23 centre (0, 0) radius 1.3 clockwise from (-0.9377, -0.9004) to (0.9377, -0.9004)
  arc A24 centre (0, -0.7479) radius 0.95 clockwise from (0.9377, -0.9004) to (-0.9377, -0.9004)
  arc A25 centre (0, 0) radius 1.3 clockwise from (-0.9377, -0.9004) to (0.9377, -0.9004)
  circle C12 centre (0, -0.7479) radius 2.0479
  circle C13 centre (0, -0.7479) radius 2.5
  arc A26 centre (0, 5.5521) radius 16 clockwise from (-1.5, -10.3774) to (-5.5, -9.4729)
  arc A27 centre (0, 5.5521) radius 16 clockwise from (5.5, -9.4729) to (1.5, -10.3774)
  concentric C6 C9
  concentric C2 C10
  concentric C1 C11
  equal C9 C10
  equal C9 C11
  concentric A24 C12
  tangent A25 C12
  concentric C12 C13
  dimension "d200" diameter C9 = 3.2
  dimension "d202" diameter C13 = 5
extrude "Extrusion28" cut sketch "Skizze30" profile of A23 L5 L6 C1 C2 C5 C6 C7 A25 C8 L13 L24 C9 C10 C11 A24 C12 against normal blind 9
extrude "Extrusion29" add sketch "Skizze30" profile of L5 L6 L13 L24 C12 C13 against normal blind 2
sketch "Skizze32" plane through (0, 0, 1.6372) normal (0, 0, -1) x axis (1, 0, 0)
  line L1 (1.5, 21.3076) -> (-1.5, 21.3076)
  line L2 (1.5, 23.3076) -> (1.5, 21.3076)
  line L3 (-1.5, 23.3076) -> (1.5, 23.3076)
  line L4 (-1.5, 21.3076) -> (-1.5, 23.3076)
  line L5 (1.5, 23.3076) -> (-1.5, 21.3076)
  line L6 (-1.5, 23.3076) -> (1.5, 21.3076)
  line L7 (22.377, 9.2029) -> (0, 0)
  line L8 (-23.1949, 9.5393) -> (0, 0)
  line L9 (15.8675, 7.607) -> (17.7194, 8.3686)
  line L10 (15.1939, 10.5667) -> (16.7643, 11.2125)
  line L11 (-17.7194, 8.3686) -> (-15.8675, 7.607)
  line L12 (-16.7643, 11.2125) -> (-15.1939, 10.5667)
  line L13 (18.5036, 8.6912) -> (17.7194, 8.3686)
  line L14 (16.7643, 11.2125) -> (18.5036, 8.6912)
  line L15 (-18.7289, 8.7838) -> (-17.7194, 8.3686)
  line L16 (-16.7643, 11.2125) -> (-18.7289, 8.7838)
  circle C1 centre (-20.25, -0.7479) radius 0.8
  circle C2 centre (20.25, -0.7479) radius 0.8
  circle C3 centre (0, 5.5521) radius 16
  arc A1 centre (-20.25, -0.7479) radius 3 clockwise from (-20.626, -3.7243) to (-22.1311, 1.5891)
  arc A2 centre (-21.8165, -13.1494) radius 9.5 clockwise from (-20.626, -3.7243) to (-14.3478, -7.2784)
  arc A3 centre (0, 4) radius 18.25 clockwise from (14.3478, -7.2784) to (-14.3478, -7.2784)
  arc A4 centre (21.8165, -13.1494) radius 9.5 clockwise from (14.3478, -7.2784) to (20.626, -3.7243)
  arc A5 centre (20.25, -0.7479) radius 3 clockwise from (22.1311, 1.5891) to (20.626, -3.7243)
  arc A6 centre (30.2824, 11.7161) radius 13 clockwise from (22.1311, 1.5891) to (17.6849, 8.5062)
  arc A7 centre (0, 4) radius 18.25 clockwise from (15.6348, 13.4136) to (17.6849, 8.5062)
  arc A8 centre (0, 5.5521) radius 17.5 clockwise from (-15.6348, 13.4136) to (15.6348, 13.4136)
  arc A9 centre (0, 4) radius 18.25 clockwise from (-17.6849, 8.5062) to (-15.6348, 13.4136)
  arc A10 centre (-30.2824, 11.7161) radius 13 clockwise from (-17.6849, 8.5062) to (-22.1311, 1.5891)
  circle C4 centre (13.5, 5.5521) radius 0.85
  circle C5 centre (-13.5, 5.5521) radius 0.85
  arc A11 centre (0, 5.5521) radius 16 clockwise from (-5.5, -9.4729) to (5.5, -9.4729)
  arc A12 centre (0, 4) radius 18.25 clockwise from (-17.6849, 8.5062) to (-15.6348, 13.4136)
  arc A13 centre (0, 4) radius 18.25 clockwise from (15.6348, 13.4136) to (17.6849, 8.5062)
  arc A14 centre (30.2824, 11.7161) radius 13 clockwise from (22.1311, 1.5891) to (17.6849, 8.5062)
  arc A15 centre (-30.2824, 11.7161) radius 13 clockwise from (-17.6849, 8.5062) to (-22.1311, 1.5891)
  circle C6 centre (0, 5.5521) radius 16
  circle C7 centre (0, 5.5521) radius 17.5
  point P24 (0, 22.3076)
  point P1 (0, 0)
  point P27 (0, 0)
  point P25 (13.5, 5.5521)
  point P26 (-13.5, 5.5521)
  point P30 (17.7194, 8.3686)
  point P31 (15.8675, 7.607)
  point P32 (16.7643, 11.2125)
  point P33 (15.1939, 10.5667)
  point P34 (-15.8675, 7.607)
  point P35 (-17.7194, 8.3686)
  point P36 (-15.1939, 10.5667)
  point P37 (-16.7643, 11.2125)
  point P17 (-15.6348, 13.4136)
  point P22 (1.5, 23.3076)
  point P23 (-1.5, 23.3076)
  horizontal L1
  perpendicular L1 L2
  parallel L1 L3
  parallel L2 L4
  coincident L5 P24
  coincident L6 P24
  vertical P1 P24
  coincident P1 P27
  coincident P25 L7
  coincident P26 L8
  coincident A7 P30
  coincident C3 P31
  coincident A7 P32
  coincident C3 P33
  parallel L9 L10
  parallel L7 L9
  coincident C3 P34
  coincident A9 P35
  coincident C3 P36
  coincident A9 P37
  parallel L8 L11
  parallel L11 L12
  concentric A11 C6
  coincident P34 C6
  concentric C6 C7
  coincident P17 C7
  parallel L9 L13
  parallel L11 L15
  dimension "d207" distance P22 P23 = 3
  dimension "d214" distance P30 P32 = 3
  dimension "d215" distance L7 P30 = 1
  dimension "d216" distance L8 P35 = 1
  dimension "d218" distance P35 P37 = 3
extrude "Extrusion30" cut sketch "Skizze32" profile of C3 A6 A7 A8 A9 A10 L2 L4 L9 L10 L11 L12 A11 A12 A13 A14 A15 C6 C7 L13 L15 against normal blind 1.5
chamfer "Fase1" distance 3
fillet "Abrundung15" radius 12.5
chamfer "Fase2" distance 0.5
delete_face "Fläche löschen16"
sketch "Skizze33" plane through (0, 0, 0) normal (1, 0, 0) x axis (0, 1, 0)
  line L1 (-5, -13.0628) -> (-22, -13.0628)
  line L2 (-5, -20.0628) -> (-5, -13.0628)
  line L3 (-22, -20.0628) -> (-5, -20.0628)
  line L4 (-22, -13.0628) -> (-22, -20.0628)
  line L5 (-23, -20.5628) -> (-4.5, -20.5628)
  point P2 (-22, -13.0628)
  point P3 (-5, -13.0628)
  point P4 (-22, -20.0628)
  point P7 (-5, -20.0628)
  point P5 (-4.5, -20.5628)
  horizontal L1
  vertical L2
  horizontal L3
  vertical L4
  dimension "d223" distance P2 P3 = 17
  dimension "d224" distance P2 P4 = 7
  dimension "d227" distance L5 P7 = 0.5
  dimension "d228" distance P5 P7 = 0.5
extrude "Extrusion31" cut sketch "Skizze33" distance 23
sketch "Skizze34" plane through (0, 0, -20.0628) normal (0, 0, 1) x axis (-1, 0, 0)
  curve K1 (-16.0604, -5.68) -> (-5.3854, -16.1931)
  curve K2 (5.3854, -16.1932) -> (16.0607, -5.6798)
  line L1 (18.5076, 5) -> (8.7467, 5)
  curve K3 (18.5076, 5) -> (6.0003, 22)
  line L2 (-6.0006, 22) -> (6.0003, 22)
  curve K4 (-6.0006, 22) -> (-18.5081, 5)
  line L3 (-8.7467, 5) -> (-18.5081, 5)
  line L4 (0, 5) -> (0, 22)
  line L5 (-7, 21.75) -> (7, 21.75)
  line L6 (-7, 5.25) -> (-7, 21.75)
  line L7 (7, 5.25) -> (-7, 5.25)
  line L8 (7, 21.75) -> (7, 5.25)
  line L9 (-7, 5.25) -> (7, 21.75)
  line L10 (7, 5.25) -> (-7, 21.75)
  line L11 (7, 5.25) -> (-7, 5.25)
  line L12 (7, 3.7198) -> (7, 5.25)
  line L13 (-7, 3.7198) -> (7, 3.7198)
  line L14 (-7, 5.25) -> (-7, 3.7198)
  line L15 (-6.0006, 22) -> (6.0003, 22)
  line L16 (-6.0006, 21.75) -> (-6.0006, 22)
  line L17 (6.0003, 21.75) -> (-6.0006, 21.75)
  line L18 (6.0003, 22) -> (6.0003, 21.75)
  line L19 (6.0003, 21.75) -> (-6.0006, 21.75)
  line L20 (6.0003, 19.75) -> (6.0003, 21.75)
  line L21 (-6.0006, 19.75) -> (6.0003, 19.75)
  line L22 (-6.0006, 21.75) -> (-6.0006, 19.75)
  line L23 (7, 5.25) -> (-7, 5.25)
  line L24 (7, 7.25) -> (7, 5.25)
  line L25 (-7, 7.25) -> (7, 7.25)
  line L26 (-7, 5.25) -> (-7, 7.25)
  arc A1 centre (-12.9, 0) radius 6.5 clockwise from (-8.7467, 5) to (-16.0604, -5.68)
  arc A2 centre (0, -12.5535) radius 6.5 clockwise from (-5.3854, -16.1931) to (5.3854, -16.1932)
  arc A3 centre (12.9, 0) radius 6.5 clockwise from (16.0607, -5.6798) to (8.7467, 5)
  circle C1 centre (0, 0) radius 3.5
  point P22 (0, 13.5)
  point P28 (-6.0006, 21.75)
  point P12 (6.0003, 22)
  point P26 (6.0003, 22)
  point P34 (7, 7.25)
  point P21 (7, 5.25)
  point P23 (7, 5.25)
  point P20 (-7, 5.25)
  point P19 (-7, 21.75)
  point P32 (-6.0006, 19.75)
  point P35 (-7, 7.25)
  horizontal L5
  perpendicular L5 L6
  parallel L5 L7
  parallel L6 L8
  coincident L9 P22
  coincident L10 P22
  coincident L4 P22
  midpoint L4 P22
  horizontal L11
  vertical L12
  horizontal L13
  vertical L14
  horizontal L15
  vertical L16
  horizontal L17
  vertical L18
  coincident L5 P28
  coincident P12 P26
  horizontal L19
  vertical L20
  horizontal L21
  vertical L22
  horizontal L23
  vertical L24
  horizontal L25
  vertical L26
  coincident L8 P34
  coincident P21 P23
  dimension "d231" distance P20 P21 = 14
  dimension "d232" distance P19 P20 = 16.5
  dimension "d233" distance P28 P32 = 2
  dimension "d234" distance P20 P35 = 2
extrude "Extrusion33" add sketch "Skizze34" profile of L4 L11 L12 L13 L14 L23 along normal blind 2
extrude "Extrusion34" add sketch "Skizze34" profile of L2 L4 L11 L15 L16 L17 L18 L19 L20 L21 L22 L23 L24 L25 L26 along normal blind 1
fillet "Abrundung16" radius 1
sketch "Skizze35" plane through (0, 0, 1.6372) normal (0, 0, 1) x axis (-1, 0, 0)
  line L1 (6.0757, -10.8643) -> (-6.0757, -10.8643)
  curve K1 (6.0757, -10.8643) -> (6.8609, -10.5469)
  curve K2 (-6.8609, -10.5469) -> (-6.0757, -10.8643)
  line L2 (1.5, -11.0612) -> (1.5, -13.0221)
  line L3 (5.5, -11.0612) -> (1.5, -11.0612)
  line L4 (5.5, -13.0221) -> (5.5, -11.0612)
  line L5 (1.5, -13.0221) -> (5.5, -13.0221)
  line L6 (-1.5, -13.0221) -> (-1.5, -11.0612)
  line L7 (-5.5, -13.0221) -> (-1.5, -13.0221)
  line L8 (-5.5, -11.0612) -> (-5.5, -13.0221)
  line L9 (-1.5, -11.0612) -> (-5.5, -11.0612)
  line L10 (-6.0757, -10.8643) -> (6.0757, -10.8643)
  curve K3 (-6.0757, -10.8643) -> (-10.2002, -11.7978)
  line L11 (-21, -11.7978) -> (-10.2002, -11.7978)
  line L12 (-22.5, -18.5547) -> (-22.5, -12.3457)
  line L13 (21, -19.1025) -> (-21, -19.1025)
  line L14 (22.5, -12.3457) -> (22.5, -18.5547)
  line L15 (10.2002, -11.7978) -> (21, -11.7978)
  curve K4 (10.2002, -11.7978) -> (6.0757, -10.8643)
  line L16 (-5.5, -9.4729) -> (-5.5, -11.0612)
  line L17 (-1.5, -9.4729) -> (-1.5, -11.0612)
  line L18 (-5.5, -9.4729) -> (-1.5, -9.4729)
  line L19 (-1.5, -11.0612) -> (-5.5, -11.0612)
  line L20 (5.5, -11.0612) -> (1.5, -11.0612)
  line L21 (1.5, -9.4729) -> (5.5, -9.4729)
  line L22 (1.5, -11.0612) -> (1.5, -9.4729)
  line L23 (5.5, -11.0612) -> (5.5, -9.4729)
  line L24 (1.5, -13.0221) -> (-1.5, -13.0221)
  line L25 (-1.5, -9.4729) -> (1.5, -9.4729)
  arc A1 centre (0, 5.5521) radius 17.5 clockwise from (-6.8609, -10.5469) to (6.8609, -10.5469)
  circle C1 centre (0, 5.5521) radius 16
  closed curve K5 centre (-21, -12.3457)
  closed curve K6 centre (-21, -18.5547)
  closed curve K7 centre (21, -18.5547)
  closed curve K8 centre (21, -12.3457)
  closed curve K9 centre (-20.25, -18.1895)
  closed curve K10 centre (20.25, -18.1895)
  closed curve K11 centre (-20.25, -12.7109)
  closed curve K12 centre (20.25, -12.7109)
  point P14 (-5.5, -11.0612)
  point P35 (-5.5, -11.0612)
  point P36 (-5.5, -9.4729)
  point P11 (-1.5, -11.0612)
  point P37 (-1.5, -11.0612)
  point P39 (-1.5, -11.0612)
  point P8 (1.5, -11.0612)
  point P40 (1.5, -11.0612)
  point P9 (5.5, -11.0612)
  point P41 (5.5, -11.0612)
  point P42 (5.5, -9.4729)
  point P12 (-1.5, -13.0221)
  point P44 (-1.5, -13.0221)
  point P7 (1.5, -13.0221)
  point P45 (1.5, -13.0221)
  coincident P14 P35
  coincident C1 P36
  perpendicular L10 L16
  coincident P11 P37
  perpendicular L1 L17
  perpendicular L16 L18
  coincident P11 P39
  coincident P8 P40
  coincident P9 P41
  coincident C1 P42
  parallel L10 L21
  perpendicular L20 L22
  perpendicular L20 L23
  coincident P12 P44
  coincident P7 P45
extrude "Extrusion35" cut sketch "Skizze35" profile of L1 C1 L10 L16 L17 L22 L23 to an object
sketch "Skizze36" plane through (0, 9.9717, 3.9123) normal (0, 0.9309, 0.3652) x axis (-1, 0, 0)
  line L1 (1.5, -2.983) -> (1.5, -8.3521)
  line L2 (5.5, -2.983) -> (1.5, -2.983)
  line L3 (5.5, -8.3521) -> (5.5, -2.983)
  line L4 (1.5, -8.3521) -> (5.5, -8.3521)
  line L5 (-1.5, -8.3521) -> (-1.5, -2.983)
  line L6 (-5.5, -2.983) -> (-5.5, -8.3521)
  line L7 (-1.5, -2.983) -> (-5.5, -2.983)
  line L8 (-6.0757, -2.4439) -> (-5.5, -2.4439)
  curve K1 (-6.0757, -2.4439) -> (-10.2002, -5)
  line L9 (-21, -5) -> (-10.2002, -5)
  line L10 (-22.5, -23.5) -> (-22.5, -6.5)
  line L11 (21, -25) -> (-21, -25)
  line L12 (22.5, -6.5) -> (22.5, -23.5)
  line L13 (10.2002, -5) -> (21, -5)
  curve K2 (10.2002, -5) -> (6.0757, -2.4439)
  line L14 (-5.5, -1.9357) -> (-5.5, -2.4439)
  line L15 (5.5, -2.4439) -> (5.5, -1.9357)
  line L16 (6.0757, -2.4439) -> (5.5, -2.4439)
  curve K3 (6.0757, -2.4439) -> (6.8609, -2.328)
  curve K4 (-6.8609, -2.328) -> (-6.0757, -2.4439)
  line L17 (-5.5, -2.4439) -> (-6.0757, -2.4439)
  line L18 (-5.5, -8.3521) -> (-1.5, -8.3521)
  line L19 (5.5, -2.4439) -> (6.0757, -2.4439)
  line L20 (5.5, -2.983) -> (5.5, -2.4439)
  line L21 (-5.5, -2.983) -> (-5.5, -2.4439)
  line L22 (1.5, -2.983) -> (-1.5, -2.983)
  line L23 (5.5, -2.4439) -> (-5.5, -2.4439)
  line L24 (1.5, -8.3521) -> (-1.5, -8.3521)
  arc A1 centre (-21, -6.5) radius 1.5 clockwise from (-22.5, -6.5) to (-21, -5)
  arc A2 centre (-21, -23.5) radius 1.5 clockwise from (-21, -25) to (-22.5, -23.5)
  arc A3 centre (21, -23.5) radius 1.5 clockwise from (22.5, -23.5) to (21, -25)
  arc A4 centre (21, -6.5) radius 1.5 clockwise from (21, -5) to (22.5, -6.5)
  circle C1 centre (-20.25, -22.5) radius 0.5
  circle C2 centre (20.25, -22.5) radius 0.5
  circle C3 centre (-20.25, -7.5) radius 0.5
  circle C4 centre (20.25, -7.5) radius 0.5
  closed curve K5 centre (0, 3.5519)
  closed curve K6 centre (0, 3.5519)
  point P36 (5.5, -2.4439)
  point P41 (5.5, -2.4439)
  point P4 (5.5, -2.983)
  point P42 (5.5, -2.983)
  point P32 (-5.5, -2.4439)
  point P43 (-5.5, -2.4439)
  point P9 (-5.5, -2.983)
  point P44 (-5.5, -2.983)
  point P6 (-1.5, -2.983)
  point P45 (-1.5, -2.983)
  point P3 (1.5, -2.983)
  point P46 (1.5, -2.983)
  point P27 (5.5, -2.4439)
  point P47 (5.5, -2.4439)
  point P7 (-1.5, -8.3521)
  point P48 (-1.5, -8.3521)
  point P2 (1.5, -8.3521)
  point P49 (1.5, -8.3521)
  coincident P36 P41
  coincident P4 P42
  coincident P32 P43
  coincident P9 P44
  coincident P6 P45
  coincident P3 P46
  coincident P27 P47
  coincident P7 P48
  coincident P2 P49
extrude "Extrusion36" cut sketch "Skizze36" profile of L1 L2 L3 L4 L5 L6 L7 L18 L20 L21 L22 L23 L24 against normal blind 0.3
delete_face "Fläche löschen17"
fillet "Abrundung17" radius 1
named bodies: "Tachoscheibe", "Steppermotor", "Adapter", "Unterteil", "Fuss (1)", "Fuss (2)", "Fuss (3)"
